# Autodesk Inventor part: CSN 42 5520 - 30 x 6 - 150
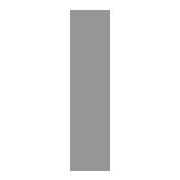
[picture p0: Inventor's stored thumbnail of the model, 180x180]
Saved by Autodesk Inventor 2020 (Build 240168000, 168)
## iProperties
Created: 2019-01
Part Number: CSN 42 5520 - 30 x 6 - 150
Material: Ocel, měkká
Description: Tyč
Document SubType Name: Modeling
Standard: CSN 42 5520
Designer: doma
Standards Organization: CSN
Language: cs-CZ
Size Designation: 30 x 6 - 150
Categories: <MemberInstance><Categories><Category DisplayName="Konstrukční profily" InternalName="089c4875-fa83-4c05-b084-43b9cc11f5ed" Mnemonic="GRDR"><CategoryParameter D
Stock Number: 30 x 6
Density: 7.85 g/cm^3
Appearance: Purpurová
Mass: 278.124 g
Surface Area: 147.773 cm^2
Volume: 35.4298 cm^3
IsCustomPart: 1
G_L: 150,000 mm
Author: doma
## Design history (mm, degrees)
node "Počáteční rovina"
node "Koncová rovina"
sketch "Náčrt"
  geometry: L1 (3, -15)-(-3, -15); L2 (-3, -15)-(-3, 15); L3 (-3, 15)-(3, 15); L4 (3, 15)-(3, -15); L5 (-6, 0)-(8, 0); L6 (0, -30)-(0, 40); L7 (0, 54)-(0, -44) reference; L8 (-9.2, 0)-(13.2, 0) reference
  constraints: 12 end point, 2 collinear, 2 parallel, 1 horizontal, 1 perpendicular
  dimensions: "d0" = 30 distance between parallel lines of L3 L1 (= G_W); "d1" = 6 distance between parallel lines of L4 L2 (= G_H); "d4" = 3 distance between parallel lines of L6 L4 (= 0.5 x d1); "d5" = 15 distance between parallel lines of L5 L3 (= 0.5 x d0)
extrude "Těleso" new body sketch "Náčrt" stored distance "d2" = 200; taper "d3" = 0 deg
node "Driven Length"
  sketch "Sketch3"
    geometry: L1 (0, 0)-(10, 0) reference
    constraints: 2 end point, 1 horizontal
  workplane "Work Plane3"
  sketch "Sketch4"
    geometry: L1 (-2, 0)-(12, 0) reference; L2 (-2, 150)-(12, 150) reference
    dimensions: "d9" = 150 distance between parallel lines of L1 L2 (derived)
sketch "Náčrt6"
  geometry: L1 (0, 0)-(0, 30) reference; L2 (0, 15)-(15, 15); 2 further points
  constraints: 2 end point, 1 coincident, 1 horizontal, 1 midpoint
  dimensions: "d20" = 15 distance of L2.start L2.end
hole "Díra2" sketch "Náčrt6" at (15, 15) diameter "d21" = 11; stored, may be unused: countersink angle "d25" = 90 deg, drill point angle "d27" = 118 deg; dims "d22" = 6, "d23" = 4, "d24" = 2, "d26" = 8
chamfer "Zkosení1" distance "d28" = 2; stored, may be unused: second distance "d29" = 2, angle "d30" = 45 deg; dims "d31" = 130, "d32" = 70, "d33" = 0 (derived)
body "Solid1"
other parameters: "G_W" = 30 [user parameter; used in 1 equation term], "G_H" = 6 [user parameter; used in 1 equation term], "G_L" = 150 (= d9) [user parameter], "G_OFFSET_START" = 0 [user parameter; used in 1 equation term], "G_OFFSET_END" = 0 [user parameter; used in 1 equation term], "d6" = 0 (computed from G_OFFSET_START), "d8" = 90 deg
